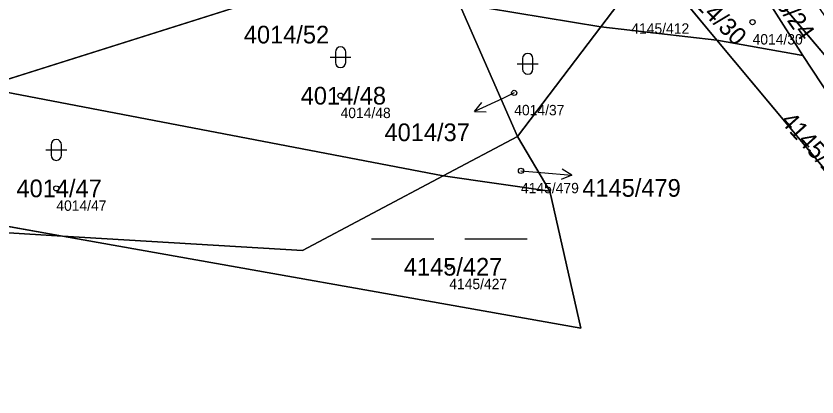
# Model space of a CAD drawing. Extents: x -739214 to -733252, y -1147612 to -1142842.
# Drawn here: x -735990.2 to -735913, y -1146738.8 to -1146702.1 of the extents above; entities that cross this region are included whole.
import ezdxf

# ---------------------------------------------------------------- set-up
doc = ezdxf.new("R2010")
doc.units = 0
for name, color, linetype in [('Definiční body', 7, 'Continuous'), ('Hranice parcel', 7, 'Continuous'), ('Parcelní čísla', 7, 'Continuous'), ('Polygon parcely', 7, 'Continuous'), ('Pop  PČ popisy', 7, 'Continuous'), ('Značky kultur', 7, 'Continuous')]:
    doc.layers.add(name, color=color, linetype=linetype)

msp = doc.modelspace()

# ---------------------------------------------------------------- linework, layer by layer
at = {"layer": 'Definiční body'}
for centre in [(-735919.22, -1146702.69), (-735958.91, -1146709.77), (-735942.18, -1146709.5), (-735941.53, -1146717), (-735986.29, -1146718.69), (-735948.44, -1146726.23)]:
    msp.add_circle(centre, 0.25, dxfattribs=at)
at = {"layer": 'Hranice parcel'}
for p, q in [((-735914.37, -1146705.91), (-735920.56, -1146696.14)), ((-735933.84, -1146703.13), (-735928.83, -1146696.54)), ((-735928.22, -1146697.74), (-735922.65, -1146704.42)), ((-735960.89, -1146698.69), (-735993.5, -1146708.99)), ((-735902.19, -1146717.78), (-735917.6, -1146699.56)), ((-735947.49, -1146700.89), (-735933.84, -1146703.13)), ((-735947.49, -1146700.89), (-735941.86, -1146713.69)), ((-735941.86, -1146713.69), (-735933.84, -1146703.13)), ((-735933.84, -1146703.13), (-735922.65, -1146704.42)), ((-735922.65, -1146704.42), (-735914.37, -1146705.91)), ((-735922.65, -1146704.42), (-735909.76, -1146719.85)), ((-735949.02, -1146717.49), (-735993.5, -1146708.99)), ((-735949.02, -1146717.49), (-735941.86, -1146713.69)), ((-735941.86, -1146713.69), (-735938.75, -1146718.95)), ((-735938.75, -1146718.95), (-735949.02, -1146717.49)), ((-735985.68, -1146723.28), (-736014.38, -1146718.18))]:
    msp.add_line(p, q, dxfattribs=at)
for points in [[(-735898.88, -1146728.02), (-735904.33, -1146721.13), (-735914.37, -1146705.91)], [(-735985.68, -1146723.28), (-735962.58, -1146724.68), (-735949.02, -1146717.49)], [(-735938.75, -1146718.95), (-735935.75, -1146732.14), (-735985.68, -1146723.28)], [(-736031.93, -1146726.58), (-736007.65, -1146721.94), (-735985.68, -1146723.28)]]:
    msp.add_lwpolyline(points, dxfattribs=at)
at = {"layer": 'Polygon parcely'}
for points in [[(-736116.2, -1146666.46), (-736124.81, -1146671.78), (-736132.77, -1146682.87), (-735993.5, -1146708.99), (-735960.89, -1146698.69)], [(-735933.84, -1146703.13), (-735928.83, -1146696.54), (-735934.08, -1146686.22), (-735935.86, -1146681.2), (-735937.31, -1146681.05), (-735953.23, -1146692.97), (-735954.46, -1146693.89), (-735947.49, -1146700.89)], [(-735930.31, -1146684.88), (-735931.19, -1146682.19), (-735935.86, -1146681.2), (-735934.08, -1146686.22), (-735928.83, -1146696.54), (-735928.22, -1146697.74), (-735922.65, -1146704.42), (-735914.37, -1146705.91), (-735920.56, -1146696.14)], [(-735909.5, -1146706.17), (-735922.06, -1146687.62), (-735917.6, -1146699.56), (-735902.19, -1146717.78)], [(-735893.09, -1146729.71), (-735898.63, -1146721.44), (-735902.19, -1146717.78), (-735917.6, -1146699.56), (-735920.56, -1146696.14), (-735914.37, -1146705.91), (-735904.33, -1146721.13), (-735898.88, -1146728.02), (-735894.56, -1146729.63)], [(-735922.65, -1146704.42), (-735928.22, -1146697.74), (-735928.83, -1146696.54), (-735933.84, -1146703.13)], [(-735947.49, -1146700.89), (-735960.89, -1146698.69), (-735993.5, -1146708.99), (-735949.02, -1146717.49), (-735941.86, -1146713.69)], [(-735941.86, -1146713.69), (-735933.84, -1146703.13), (-735947.49, -1146700.89)], [(-735914.07, -1146753.35), (-735903.64, -1146747.89), (-735889.03, -1146740.23), (-735892.16, -1146736.62), (-735898.88, -1146728.02), (-735901.57, -1146727.02), (-735909.76, -1146719.85), (-735922.65, -1146704.42), (-735933.84, -1146703.13), (-735941.86, -1146713.69), (-735938.75, -1146718.95), (-735935.75, -1146732.14), (-735985.68, -1146723.28), (-736007.65, -1146721.94), (-736031.93, -1146726.58), (-736043.74, -1146728.83), (-736064.23, -1146728.39), (-736076.7, -1146728.12), (-736081.12, -1146733.26), (-736090.37, -1146744), (-736100.78, -1146756.09), (-735962.39, -1146778.66), (-735945.61, -1146769.88), (-735925.38, -1146759.28)], [(-735909.76, -1146719.85), (-735901.57, -1146727.02), (-735898.88, -1146728.02), (-735904.33, -1146721.13), (-735914.37, -1146705.91), (-735922.65, -1146704.42)], [(-735962.58, -1146724.68), (-735949.02, -1146717.49), (-735993.5, -1146708.99), (-736010.89, -1146714.48), (-736014.38, -1146718.18), (-735985.68, -1146723.28)], [(-735941.86, -1146713.69), (-735949.02, -1146717.49), (-735938.75, -1146718.95)], [(-735949.02, -1146717.49), (-735962.58, -1146724.68), (-735985.68, -1146723.28), (-735935.75, -1146732.14), (-735938.75, -1146718.95)], [(-736007.65, -1146721.94), (-735985.68, -1146723.28), (-736014.38, -1146718.18), (-736016.5, -1146720.43), (-736047, -1146722.91), (-736050.6, -1146723.02), (-736031.93, -1146726.58)]]:
    msp.add_lwpolyline(points, close=True, dxfattribs=at)
at = {"layer": 'Pop  PČ popisy'}
for p, q in [((-735942.18, -1146709.5), (-735943.29, -1146710.03)), ((-735943.29, -1146710.03), (-735946.01, -1146711.298)), ((-735946.01, -1146711.298), (-735945.314, -1146710.421)), ((-735946.01, -1146711.298), (-735944.891, -1146711.329)), ((-735941.53, -1146717), (-735939.61, -1146717.17)), ((-735939.61, -1146717.17), (-735936.62, -1146717.432)), ((-735936.62, -1146717.432), (-735937.574, -1146716.845)), ((-735936.62, -1146717.432), (-735937.662, -1146717.843))]:
    msp.add_line(p, q, dxfattribs=at)
at = {"layer": 'Značky kultur'}
for p, q in [((-735959.411, -1146705.571), (-735959.411, -1146706.572)), ((-735958.409, -1146706.572), (-735958.409, -1146705.571)), ((-735959.911, -1146706.071), (-735957.909, -1146706.071)), ((-735941.381, -1146706.201), (-735941.381, -1146707.202)), ((-735940.379, -1146707.202), (-735940.379, -1146706.201)), ((-735941.881, -1146706.701), (-735939.879, -1146706.701)), ((-735987.291, -1146714.991), (-735985.289, -1146714.991)), ((-735986.791, -1146714.491), (-735986.791, -1146715.492)), ((-735985.789, -1146715.492), (-735985.789, -1146714.491)), ((-735955.929, -1146723.53), (-735949.929, -1146723.53)), ((-735946.929, -1146723.53), (-735940.929, -1146723.53))]:
    msp.add_line(p, q, dxfattribs=at)
for centre, start, end in [((-735958.91, -1146705.571), 0, 180), ((-735940.88, -1146706.201), 0, 180), ((-735958.91, -1146706.571), 180, 359.98789), ((-735940.88, -1146707.201), 180, 359.98789), ((-735986.29, -1146714.491), 0, 180), ((-735986.29, -1146715.491), 180, 359.98789)]:
    msp.add_arc(centre, 0.5, start, end, dxfattribs=at)

# ---------------------------------------------------------------- texts
at = {"layer": 'Definiční body'}
for s, p in [('4145/412', (-735930.9, -1146703.806)), ('4014/30', (-735919.22, -1146704.846)), ('4014/48', (-735958.91, -1146711.926)), ('4014/37', (-735942.18, -1146711.656)), ('4145/479', (-735941.53, -1146719.156)), ('4014/47', (-735986.29, -1146720.846)), ('4145/427', (-735948.44, -1146728.386))]:
    msp.add_text(s, height=1, dxfattribs=at).set_placement(p)
at = {"layer": 'Parcelní čísla'}
for s, rotation, p in [('4145/24', 305, (-735919.223, -1146697.857)), ('4014/30', 315, (-735926.651, -1146699.265)), ('4145/19', 312, (-735916.621, -1146712.271))]:
    msp.add_text(s, height=1.7, rotation=rotation, dxfattribs=at).set_placement(p)
for s, p in [('4014/52', (-735968.226, -1146704.743)), ('4014/48', (-735962.748, -1146710.62)), ('4014/37', (-735954.676, -1146714.143)), ('4014/47', (-735990.128, -1146719.54)), ('4145/479', (-735935.62, -1146719.493)), ('4145/427', (-735952.81, -1146727.08))]:
    msp.add_text(s, height=1.7, dxfattribs=at).set_placement(p)

doc.saveas('drawing.dxf')
